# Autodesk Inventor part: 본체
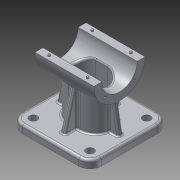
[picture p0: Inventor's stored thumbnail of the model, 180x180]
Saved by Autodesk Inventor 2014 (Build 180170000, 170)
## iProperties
Created: 2015-12
Part Number: 본체
Material: 알루미늄 6061
Document SubType Name: Modeling
Designer: mduedu
Density: 2.71 g/cm^3
Appearance: 알루미늄 - 평지
Author: mduedu
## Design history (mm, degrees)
sketch "스케치1"
  geometry: L1 (-50, -50)-(50, -50); L2 (50, -50)-(50, 50); L3 (50, 50)-(-50, 50); L4 (-50, 50)-(-50, -50); L5 (-50, -50)-(50, 50); L6 (50, -50)-(-50, 50); 2 further points
  constraints: 12 end point, 2 midpoint, 2 parallel, 1 coincident, 1 horizontal, 1 perpendicular
  dimensions: "d154" = 100 distance of L2.end L3.end; "d155" = 100 distance of L3.end L1.start
extrude "돌출1" new body sketch "스케치1" distance "d3" = 10; taper "d4" = 0 deg
sketch "스케치2"
  geometry: C1 r 32.5 at (80, 0); 1 further point
  constraints: 1 centre point, 1 horizontal alignment
  dimensions: "d5" = 65 diameter of C1; "d125" = 80 distance of C1.centre point (0, 0)
extrude "돌출2" join sketch "스케치2" stored distance "d7" = 75; taper "d8" = 0 deg
sketch "스케치3"
  geometry: L1 (-27.5, -20)-(27.5, -20); L2 (27.5, -20)-(27.5, 20); L3 (27.5, 20)-(-27.5, 20); L4 (-27.5, 20)-(-27.5, -20); L5 (-27.5, -20)-(27.5, 20); L6 (27.5, -20)-(-27.5, 20); 1 further point
  constraints: 12 end point, 2 midpoint, 2 parallel, 1 horizontal, 1 perpendicular
  dimensions: "d9" = 55 distance of L2.end L3.end; "d11" = 40 distance of L1.end L2.end
extrude "돌출3" new body sketch "스케치3" stored distance "d12" = 75; taper "d13" = 0 deg
fillet "모깎기1"
fillet "모깎기2"
feature "결합1"
  node "솔리드2"
sketch "스케치4"
  geometry: L1 (-37.5, 47.5)-(37.5, 47.5) reference; L2 (32.5, 47.5)-(39.112, 10); L3 (37.5, 47.5)-(37.5, 112.5) reference; L4 (50, 10)-(-50, 10) reference; 1 further point
  constraints: 2 end point, 2 point on line
  dimensions: "d15" = 5 distance from line of L2.start L3; "d126" = 80 deg angle of L2 L1
feature "리브1" dims "d19" = 1, "d20" = 6, "d21" = 0, "d22" = 0, "d23" = 1, "d24" = 1
feature "리브2" dims "d25" = 1, "d26" = 6, "d27" = 0, "d28" = 0, "d29" = 1, "d30" = 1
fillet "모깎기4" dims "d31" = 2
fillet "모깎기5" dims "d32" = 2
fillet "모깎기6" dims "d33" = 2
fillet "모깎기7" dims "d41" = 14
hole "구멍2" diameter "d44" = 45; stored, may be unused: countersink angle "d48" = 90 deg, drill point angle "d50" = 118 deg; dims "d42" = 10, "d43" = 10, "d45" = 6, "d46" = 4, "d47" = 2, "d49" = 8
sketch "스케치7" dims "d52" = 26.5
  geometry: L1 (0, 0)-(32.5, 0); L2 (0, 0)-(22.981, 22.981); A1 r 32.5 centre (0, 0) between (32.5, 0) and (22.981, 22.981) reference; 3 further points
  constraints: 4 end point, 2 point on circle, 1 coincident, 1 horizontal, 1 point on line, 3 other
  dimensions: "d51" = 45 deg angle of L2 L1
hole "구멍3" sketch "스케치7" at (18.738, 18.738) diameter "d54" = 2.459; stored, may be unused: countersink angle "d58" = 90 deg, drill point angle "d60" = 118 deg; dims "d55" = 8, "d56" = 4, "d57" = 2, "d59" = 10
sketch "스케치9"
  geometry: L1 (-75, 82.5)-(75, 82.5); L2 (75, 82.5)-(75, 0); L3 (75, 0)-(-75, 0); L4 (-75, 0)-(-75, 82.5); C1 r 32.5 at (0, 0) reference; 2 further points
  constraints: 8 end point, 2 parallel, 1 coincident, 1 horizontal, 1 midpoint, 1 perpendicular
  dimensions: "d71" = 50 distance edge to line of C1 L1; "d116" = 150 distance between parallel lines of L2 L4
extrude "돌출5" cut sketch "스케치9" stored distance "d73" = 0; taper "d74" = 0 deg
node "작업 평면1"
sketch "스케치10"
  geometry: L1 (-7.5, 15)-(7.5, 15); L2 (-7.5, -15)-(7.5, -15); A1 r 20 centre (-7.5, 0) between (-7.5, 20) and (-26.977, 4.545) reference; A2 r 20 centre (7.5, 0) between (26.977, 4.545) and (7.5, 20) reference; A3 r 15 centre (-7.5, 0) between (-7.5, 15) and (-7.5, -15); A4 r 15 centre (7.5, 0) between (7.5, -15) and (7.5, 15); 1 further point
  constraints: 7 point on circle, 4 end point, 4 tangent, 3 point on line, 2 centre point, 2 coincident, 1 horizontal
  dimensions: "d77" = 5 radial gap between concentric circles of A3 A1
extrude "돌출6" cut sketch "스케치10" stored distance "d78" = 50; taper "d79" = 0 deg
fillet "모깎기10" dims "d80" = 3
sketch "스케치11"
  geometry: 2 further points
  constraints: 1 coincident
hole "구멍4" sketch "스케치11" at (0, 0) diameter "d81" = 12; stored, may be unused: countersink angle "d85" = 90 deg, drill point angle "d87" = 118 deg; dims "d82" = 8, "d83" = 40, "d84" = 10, "d86" = 10
sketch "스케치12"
  geometry: C1 r 10 at (0, 0); 1 further point
  constraints: 1 centre point, 1 coincident
  dimensions: "d88" = 20 diameter of C1
extrude "돌출7" cut sketch "스케치12" distance "d89" = 5; taper "d90" = 0 deg
chamfer "모따기1" distance "d91" = 1; stored, may be unused: second distance "d92" = 2, angle "d93" = 45 deg
fillet "모깎기11" dims "d94" = 0.5
fillet "모깎기12" dims "d115" = 0.3
sketch "스케치15"
  geometry: L1 (-75, 55)-(-75, 65) reference; L2 (0, 65)-(0, 55) reference; L3 (-75, 60)-(0, 60); C1 r 1.5 at (-62, 60); 1 further point
  constraints: 2 end point, 2 midpoint, 1 centre point, 1 point on line
  dimensions: "d117" = 3 diameter of C1; "d118" = 13 distance from line of C1.centre L1
extrude "돌출8" join sketch "스케치15" distance "d119" = 1.8; taper "d120" = 0 deg
chamfer "모따기2" distance "d121" = 0.5; stored, may be unused: second distance "d122" = 2, angle "d123" = 45 deg
sketch "스케치19"
  geometry: A1 r 14 centre (-36, -36) between (-50, -36) and (-36, -50) reference; A2 r 14 centre (-36, 36) between (-36, 50) and (-50, 36) reference; A3 r 14 centre (36, 36) between (50, 36) and (36, 50) reference; A4 r 14 centre (36, -36) between (36, -50) and (50, -36) reference; 5 further points
  constraints: 4 coincident
hole "구멍9" sketch "스케치19" at (-36, -36), (36, -36), (36, 36), (-36, 36) diameter "d156" = 10; stored, may be unused: countersink angle "d160" = 90 deg, drill point angle "d162" = 0 deg; dims "d157" = 6, "d158" = 4, "d159" = 2, "d161" = 8
node "솔리드1"
sketch "스케치5"
  geometry: L1 (10, 35)-(56.569, 22.522); L2 (10, 20)-(54.383, 20) reference; L3 (10, -50)-(10, 50) reference; A1 r 32.5 centre (80, 0) between (56.569, 22.522) and (54.383, 20) reference; 1 further point
  constraints: 2 end point, 1 point on circle, 1 point on line
  dimensions: "d128" = 15 distance of L1.start L2.start
mirror "대칭1"
mirror "대칭2"
pattern_circular "원형 패턴1" dims angle "d62" = 360 deg
mirror "대칭3"
mirror "대칭5"
mirror "대칭6"
